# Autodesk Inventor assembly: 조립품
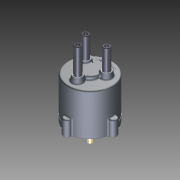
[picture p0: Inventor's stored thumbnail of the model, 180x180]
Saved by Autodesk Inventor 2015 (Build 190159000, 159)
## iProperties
Created: 2015-05
Part Number: 조립품
Document SubType Name: Assembly
Designer: Young-Hwan
Mass: 2156.77 g
Surface Area: 1801.21 cm^2
Volume: 438.523 cm^3
Density: 4.91825 g/cm^3
Author: Young-Hwan
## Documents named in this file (14)
- C:\Users\Young-Hwan\Desktop\Inventor1급\조립품.iam
- C:\Users\Young-Hwan\Desktop\Inventor1급\몸체.ipt
- C:\Users\Young-Hwan\Desktop\Inventor1급\커버.ipt
- C:\Users\Young-Hwan\Desktop\Inventor1급\메인 축.ipt
- C:\Users\Young-Hwan\Desktop\Inventor1급\판캠.ipt
- C:\Users\Young-Hwan\Desktop\Inventor1급\슬라이드 축.ipt
- C:\Users\Young-Hwan\Desktop\Inventor1급\베어링 NA 4900.ipt
- C:\Users\Young-Hwan\Desktop\Inventor1급\멈춤링 10 x 1.ipt
- C:\Users\Young-Hwan\Desktop\Inventor1급\멈춤링 22 x 1.2.ipt
- C:\Users\Young-Hwan\Desktop\Inventor1급\M5x0.5x20.ipt
- C:\Users\Young-Hwan\Desktop\Inventor1급\가변 스프링-01.ipt
- C:\Users\Young-Hwan\Desktop\Inventor1급\가변 스프링-02.ipt
- C:\Users\Young-Hwan\Desktop\Inventor1급\가변 스프링-03.ipt
- C:\Users\Young-Hwan\Desktop\Inventor1급\오일실.ipt
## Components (7 placed, 4 different names)
1. 가변 스프링-01:1
2. 가변 스프링-02:1
3. 가변 스프링-03:1
4. M5x0.5x20:1 — 각도:1
5. M5x0.5x20:2
6. M5x0.5x20:3
7. M5x0.5x20:4
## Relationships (1: Angle 1)
- 각도:1 [Angle]: M5x0.5x20:1
